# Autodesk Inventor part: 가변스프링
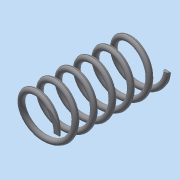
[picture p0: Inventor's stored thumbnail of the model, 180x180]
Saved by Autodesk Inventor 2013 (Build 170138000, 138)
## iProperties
Created: 2018-06
Part Number: 가변스프링
Material: 일반
Document SubType Name: Modeling
Designer: dgall
Density: 1 g/cm^3
Author: dgall
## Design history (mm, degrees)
sketch "스케치1"
  geometry: L1 (0, 0)-(0, 38); L2 (0, 38)-(8, 38); L3 (0, 0)-(8, 0); C1 r 1 at (8, 0)
  constraints: 6 end point, 1 centre point, 1 coincident, 1 parallel, 1 perpendicular, 1 vertical, 1 vertical alignment
  dimensions: "d0" = 38 distance of L1.start L1.end (derived); "d1" = 16 diameter of L2.end L1; "d2" = 2 diameter of C1
feature "코일1" sketch "스케치1" pitch "d3" = 10; turns "d5" = 6; dims "d4" = 38 (= d0), "d6" = 0, angle "d7" = 90 deg, angle "d8" = 90 deg, "d9" = 0, "d10" = 0
feature "분할1"
node "작업 평면1"
feature "분할2"
node "솔리드1"
other parameters: "d11" = 0
